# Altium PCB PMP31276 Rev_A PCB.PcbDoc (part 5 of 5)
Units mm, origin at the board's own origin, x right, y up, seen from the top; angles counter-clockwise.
Board outline 228.6 x 203.2 mm, 4 copper layers (Top Layer, Layer 1, Layer 2, Bottom Layer), stack 1.998 mm thick; 375 components, 187 nets, 994 pads, 546 vias.
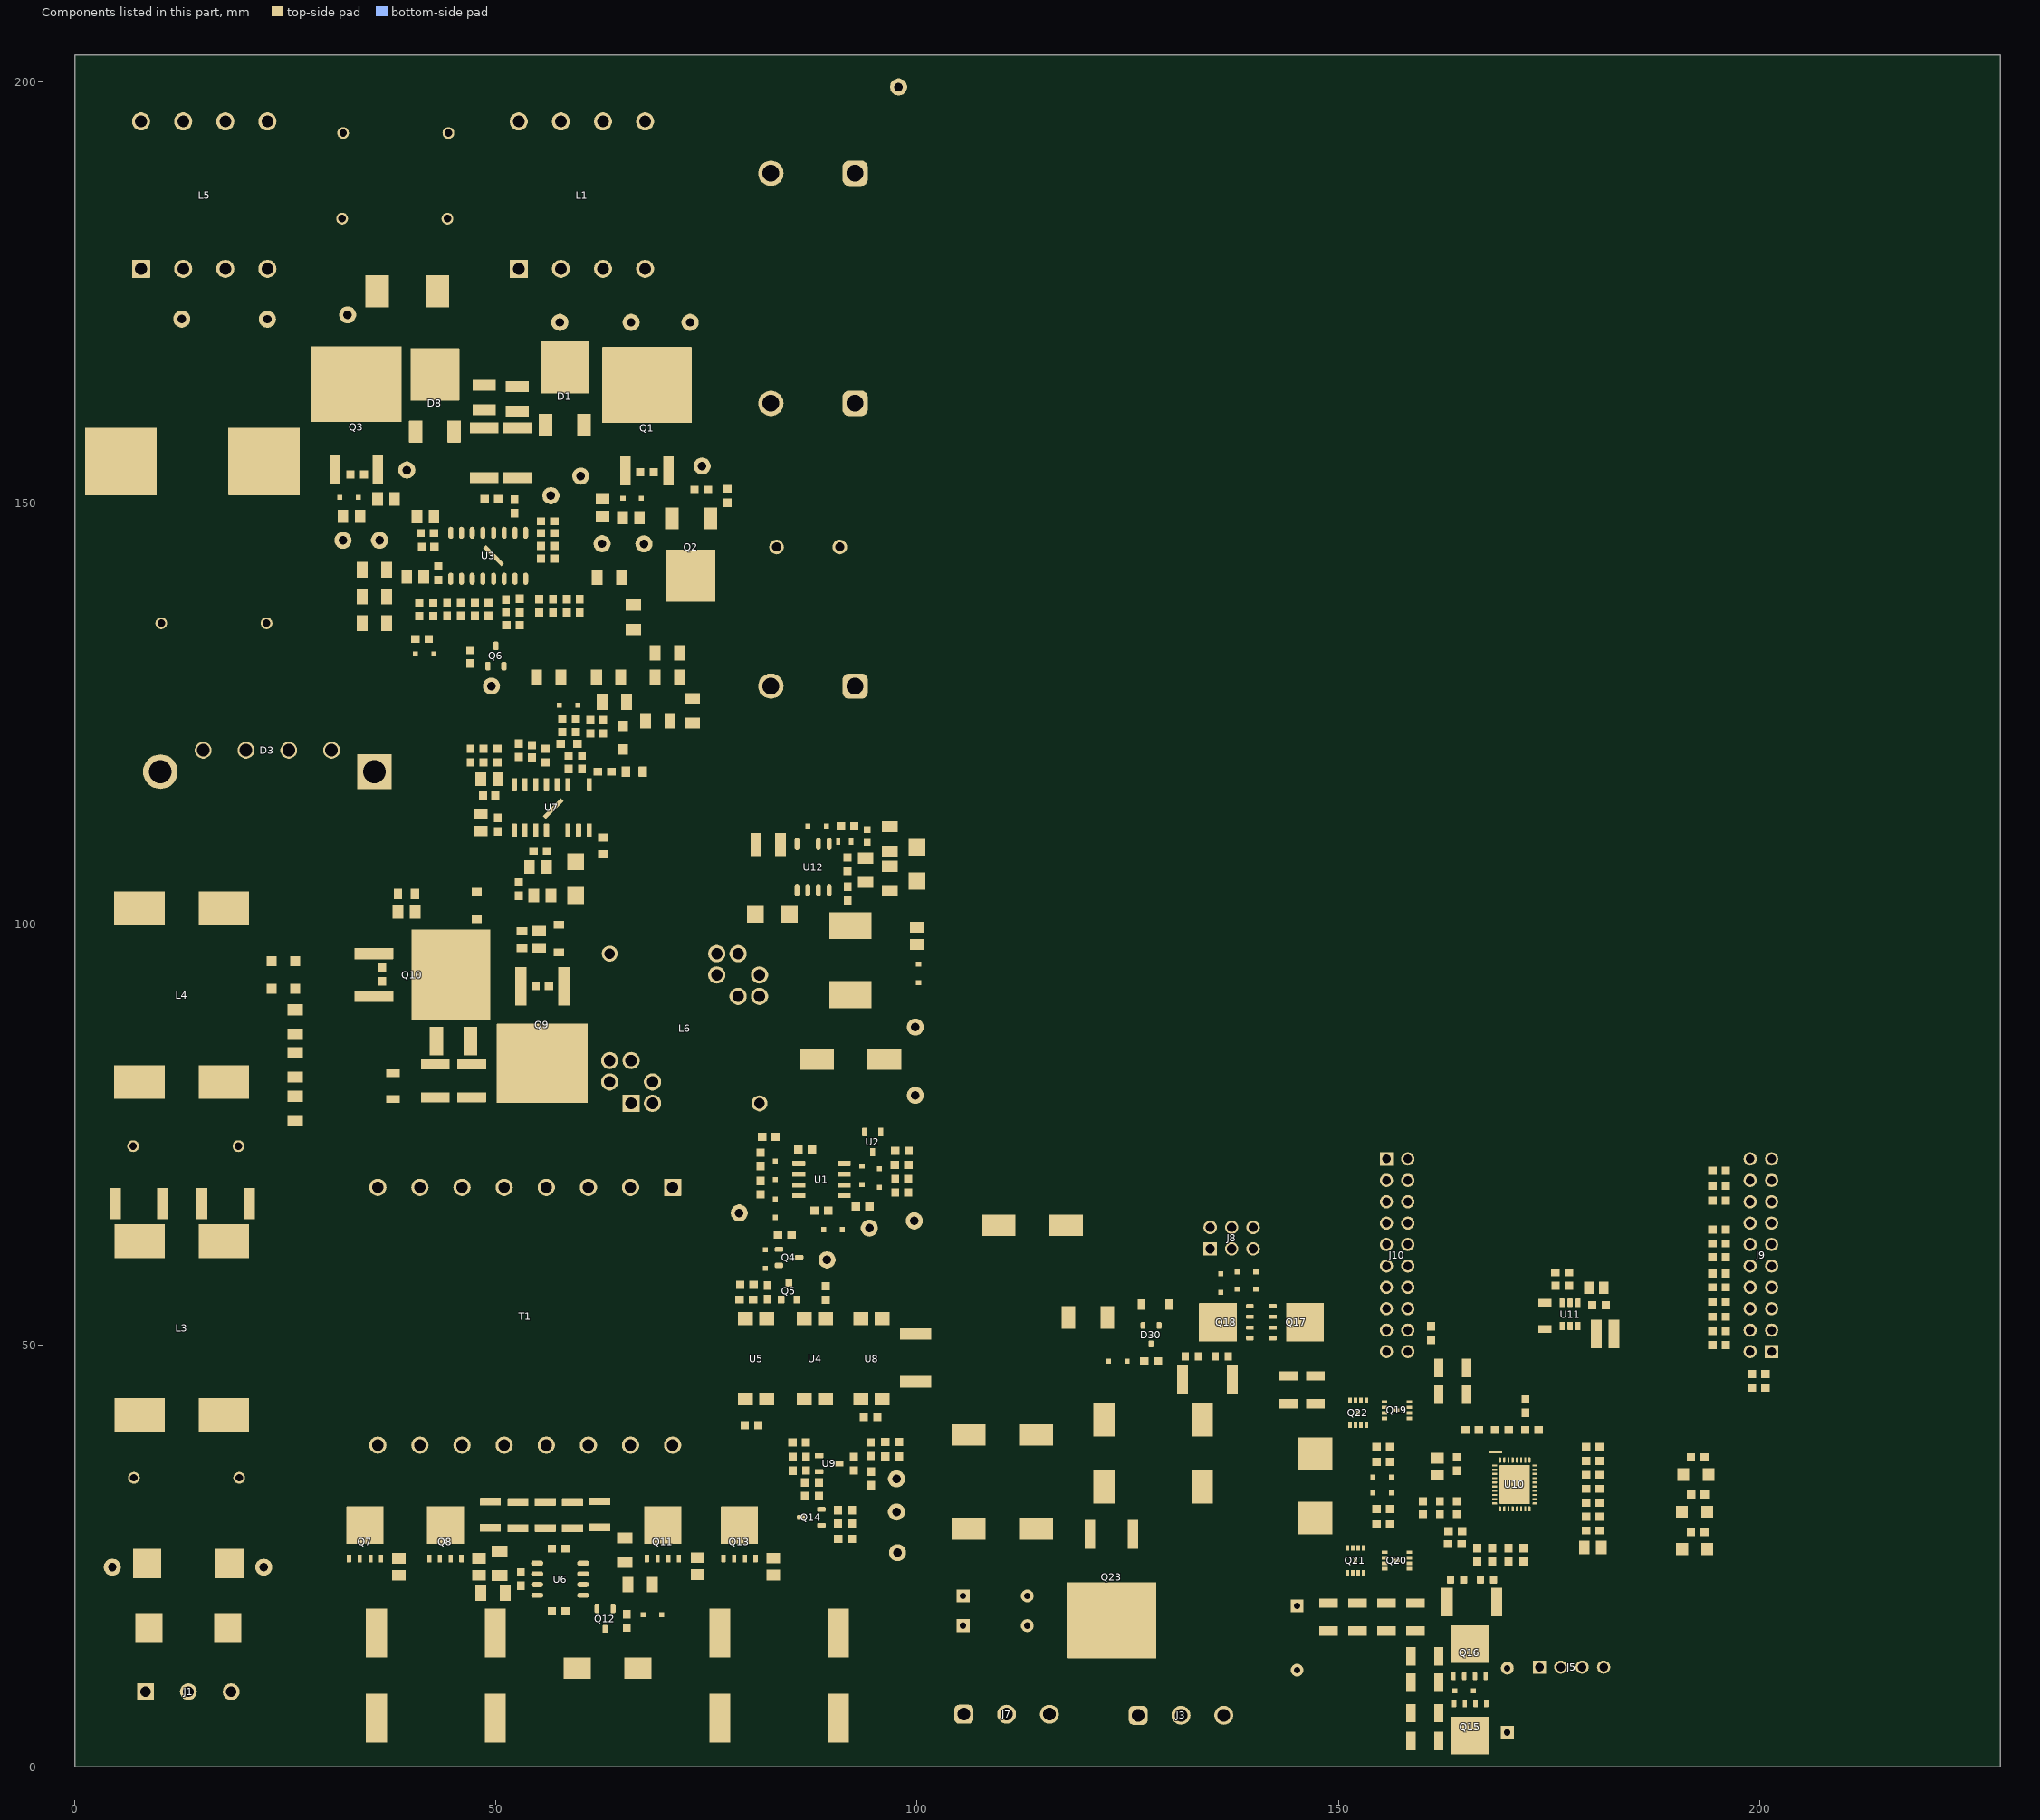
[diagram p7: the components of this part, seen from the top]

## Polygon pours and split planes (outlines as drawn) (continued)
NetC14_1 on Top Layer "TOP_LAYER_NETC14_1_P054" (solid, remove dead copper, pour order 54): 76.427,150.725 76.745,151.043 78.082,151.043 78.195,151.156 78.195,152.172 77.986,152.381 75.813,152.381 75.655,152.539 74.887,152.539 74.472,152.124 74.472,146.875 74.761,146.586 76.037,146.586 76.427,146.976
NetD11_2 on Top Layer "TOP_LAYER_NETD11_2_P053" (solid, remove dead copper, pour order 53): 18 vertices, not listed, extent 29.685,144.03 33.43,156.417
PGND on Top Layer "TOP_LAYER_PGND_P052" (solid, remove dead copper, pour order 52): 45.212,156.368 34.339,156.368 33.782,155.812 33.782,152.635 34.895,151.522 44.375,151.522 45.268,152.415
PGND on Top Layer "TOP_LAYER_PGND_P051" (solid, remove dead copper, pour order 51): 52.6,155.485 67.246,155.485 68.586,154.145 72.242,154.145 72.82,154.723 72.657,154.887 72.657,157.04 70.928,158.768 64.745,158.768 63.465,157.489 55.217,157.489 54.275,158.43 54.275,158.448 53.016,158.448 52.569,158
net_D1_3 on Top Layer "TOP_LAYER_NET_D1_3_P045" (solid, remove dead copper, pour order 45): 18 vertices, not listed, extent 59.283,158 73.895,197.231
PGND on Top Layer "TOP_LAYER_PGND_P050" (solid, remove dead copper, pour order 50): 70.356,146.28 69.193,145.118 69.193,144.02 68.356,143.182 65.886,143.182 65.886,146.025 66.673,146.812 67.799,146.812 68.336,147.349 68.336,154.723 70.318,156.706 72.122,156.706 74.053,154.774 74.053,148.343 71.99,146.28
Vpfc on Top Layer "TOP_LAYER_VPFC_P047" (solid, remove dead copper, pour order 47): 70.623,133.107 70.623,127.698 72.222,126.099 74.37,126.099 74.37,132.214 73.202,133.382 70.898,133.382
NetC1_2 on Top Layer "TOP_LAYER_NETC1_2_P046" (solid, remove dead copper, pour order 46): 17 vertices, not listed, extent 69.472,124.778 84.98,192.151
VAC on Top Layer "TOP_LAYER_VAC_P044" (solid, remove dead copper, pour order 44): 35.464,191.747 40.346,196.629 48.26,196.629 50.546,194.343 50.546,194.056 51.562,193.04 52.959,193.04 54.356,194.437 54.356,196.088 51.181,199.263 31.75,199.263 30.099,197.612 30.099,193.039 31.391,191.747
Vpfc on Top Layer "TOP_LAYER_VPFC_P043" (solid, remove dead copper, pour order 43): 21 vertices, not listed, extent 39.648,161.88 61.448,177.165
VAC on Top Layer "TOP_LAYER_VAC_P042" (solid, remove dead copper, pour order 42): 26.162,150.259 18.402,150.259 14.605,154.057 14.605,158.496 4.318,168.783 4.318,197.104 8.785,197.104 10.414,195.475 10.414,178.399 10.196,178.181 10.196,171.803 20.231,161.768 23.833,161.768 27.178,158.423 27.178,151.44
NetD8_3 on Top Layer "TOP_LAYER_NETD8_3_P039" (solid, remove dead copper, pour order 39): 18 vertices, not listed, extent 20.066,159.21 38.966,197.294
VAC on Top Layer "TOP_LAYER_VAC_P038" (solid, remove dead copper, pour order 38): 39.537,173.62 39.537,177.97 37.988,179.519 35.916,179.519 34.395,177.998 34.395,172.609 34.665,172.339 38.256,172.339
AGND1 on Top Layer "TOP_LAYER_AGND1_P037" (solid, remove dead copper, pour order 37): 58.427,142.068 41.855,142.068 39.769,144.154 39.769,146.586 40.339,147.156 41.596,147.156 41.968,146.784 41.968,144.417 42.649,143.736 54.657,143.736 56.134,145.214 56.134,146.849 56.388,147.103 57.393,147.103 58.427,146.068
AGND1 on Top Layer "TOP_LAYER_AGND1_P035" (solid, remove dead copper, pour order 35): 39.796,137.692 49.552,137.692 51.551,139.691 53.146,139.691 55.041,137.795 60.827,137.795 61.305,137.316 61.305,134.685 58.463,131.843 43.511,131.843 39.796,135.557
PGND on Top Layer "TOP_LAYER_PGND_P034" (solid, remove dead copper, pour order 34): 47.789,155.411 46.332,156.868 46.332,161.768 46.944,162.38 53.825,162.38 54.61,161.595 54.61,156.21 53.811,155.411
NetC6_2 on Top Layer "TOP_LAYER_NETC6_2_P032" (solid, remove dead copper, pour order 32): 13.688,118.991 5.08,127.599 5.08,145.776 1.016,149.84 1.016,159.438 2.36,160.782 10.196,160.782 11.938,159.04 11.938,133.512 17.266,128.184 17.266,120.142 16.115,118.991
NetD3_3 on Top Layer "TOP_LAYER_NETD3_3_P031" (solid, remove dead copper, pour order 31): 13.843,99.246 13.843,108.217 17.386,111.76 19.999,111.76 23.492,115.253 23.492,121.663 24.511,122.682 26.663,122.682 27.407,121.938 27.407,113.259 21.688,107.54 21.688,99.666
NetD3_2 on Top Layer "TOP_LAYER_NETD3_2_P030" (solid, remove dead copper, pour order 30): 3.302,97.184 10.588,97.184 11.71,98.306 11.71,108.484 16.51,113.284 18.365,113.284 22.225,117.144 22.225,122.174 21.717,122.682 19.812,122.682 18.365,121.235 18.365,119.146 16.778,117.56 15.452,117.56 3.302,105.41
NetD3_3 on Top Layer "TOP_LAYER_NETD3_3_P028" (solid, remove dead copper, pour order 28): 13.843,104.394 13.843,97.282 16.891,94.234 24.011,94.234 24.765,94.988 24.765,96.931 24.447,97.248 23.225,97.248 21.688,98.786 21.688,103.783 20.188,105.283 14.732,105.283
NetD3_2 on Top Layer "TOP_LAYER_NETD3_2_P027" (solid, remove dead copper, pour order 27): 3.302,104.648 3.302,93.583 5.826,91.059 24.13,91.059 24.765,91.694 24.765,93.084 24.266,93.583 14.498,93.583 11.688,96.393 11.71,96.415 11.71,104.254 10.681,105.283 4.434,105.283
NetC10_1 on Top Layer "TOP_LAYER_NETC10_1_P026" (solid, remove dead copper, pour order 26): 3.462,59.276 2.54,60.198 2.54,82.901 3.619,83.98 10.979,83.98 11.7,83.259 11.7,78.756 8.461,75.517 8.461,64.828 8.944,64.345 11.089,64.345 11.7,63.734 11.7,60.022 10.954,59.276
NetC11_1 on Top Layer "TOP_LAYER_NETC11_1_P025" (solid, remove dead copper, pour order 25): 5.465,20.193 3.175,22.483 3.175,43.224 6.052,46.101 11.2,46.101 12.226,45.075 12.226,23.536 8.883,20.193 8.802,20.193
NetC11_2 on Top Layer "TOP_LAYER_NETC11_2_P022" (solid, remove dead copper, pour order 22): 21.994,44.935 21.994,28.125 23.749,26.359 23.749,21.082 22.86,20.193 15.708,20.193 14.732,21.169 14.732,45.312 15.521,46.101 20.828,46.101
NetC94_2 on Layer 2 "LAYER_2_NETC94_2_P146" (solid, remove dead copper, pour order 146): 21 vertices, not listed, extent 83.82,98.035 101.05,113.284
SGND on Layer 2 "LAYER_2_SGND_P132" (solid, remove dead copper, pour order 132): 21 vertices, not listed, extent 29.782,0.723 106.813,46.482
SGND on Layer 2 "LAYER_2_SGND_P131" (solid, remove dead copper, pour order 131): 95.377,0.723 197.065,0.723 204.724,8.382 204.724,73.406 202.057,76.073 114.456,76.073 104.636,66.253 104.636,49.522 95.377,42.203
NetC75_1 on Layer 2 "LAYER_2_NETC75_1_P121" (solid, remove dead copper, pour order 121): 120.523,38.517 124.028,38.517 129.535,44.024 139.111,44.024 139.707,44.62 139.707,47.324 139.107,47.924 124.148,47.924 120.523,44.299
AGND on Layer 2 "LAYER_2_AGND_P102" (solid, remove dead copper, pour order 102): 21 vertices, not listed, extent 160.714,23.26 184.117,41.333
+24V on Layer 2 "LAYER_2_+24V_P008" (solid, remove dead copper, pour order 8): 71.665,9.271 73.189,10.795 78.74,10.795 79.738,11.793 79.738,18.71 78.522,19.926 74.491,19.926 73.66,19.095 73.66,16.924 72.356,15.62 67.08,15.62 64.456,12.996 64.456,10.166 65.351,9.271
VDS2 on Layer 2 "LAYER_2_VDS2_P082" (solid, remove dead copper, pour order 82): 73.052,40.559 82.219,31.393 82.219,26.669 81.898,26.348 64.32,26.348 63.842,26.826 63.842,31.034 64.407,31.598 64.407,39.799 65.166,40.559
VDS1 on Layer 2 "LAYER_2_VDS1_P072" (solid, remove dead copper, pour order 72): 33.712,40.57 29.782,36.64 29.782,27.27 30.693,26.359 48.226,26.359 48.226,30.155 43.539,34.841 43.539,38.338 41.307,40.57
Vpfc on Layer 2 "LAYER_2_VPFC_P049" (solid, remove dead copper, pour order 49): 84.711,123.534 78.564,123.534 68.658,113.628 68.658,111.818 65.18,111.818 49.25,95.888 49.25,73.157 50.234,72.173 73.552,72.173 73.552,101.346 97.79,125.222 97.79,131.191 88.898,128.951 88.898,127.721
Vpfc on Layer 2 "LAYER_2_VPFC_P041" (solid, remove dead copper, pour order 41): 72.319,126.002 74.229,126.002 79.534,131.307 92.757,131.307 92.757,133.678 92.45,133.985 71.501,133.985 70.623,133.107 70.623,127.698
Vpfc on Layer 2 "LAYER_2_VPFC_P029" (solid, remove dead copper, pour order 29): 17 vertices, not listed, extent 47.681,123.825 98.044,192.659
CS on Layer 2 "LAYER_2_CS_P023" (solid, remove dead copper, pour order 23): 42.037,194.062 42.037,157.644 39.583,155.19 40.722,154.051 45.215,154.051 46.536,155.372 44.921,156.987 44.921,180.356 46.834,182.269 46.834,194.562 45.583,195.813 43.788,195.813
VAC on Layer 2 "LAYER_2_VAC_P021" (solid, remove dead copper, pour order 21): 21 vertices, not listed, extent 4.97,170.307 39.537,197.104
CS on Layer 2 "LAYER_2_CS_P017" (solid, remove dead copper, pour order 17): 17 vertices, not listed, extent 18.542,118.11 55.12,158.377
+24V on Bottom Layer "Bottom Layer-+24V" (solid, remove dead copper, pour order 149): 17 vertices, not listed, extent 69.831,1.016 189.357,28.759
NetC81_1 on Bottom Layer "BOTTOM_LAYER_NETC81_1_P143" (solid, remove dead copper, pour order 143): 153.993,39.559 153.528,39.094 153.528,37.944 150.497,34.913 145.193,34.913 144.643,35.463 144.643,39.094 145.554,40.005 148.685,40.005 149.098,40.418 149.098,41.025 150.368,42.294 153.698,42.294 153.993,42
NetC80_1 on Bottom Layer "BOTTOM_LAYER_NETC80_1_P142" (solid, remove dead copper, pour order 142): 155.87,23.883 147.725,23.883 144.898,26.71 144.898,31.31 145.428,31.839 149.617,31.839 154.45,27.007 154.45,26.128 154.766,25.811 155.721,25.811 155.87,25.663
SYSTEM on Bottom Layer "BOTTOM_LAYER_SYSTEM_P108" (solid, remove dead copper, pour order 108): 18 vertices, not listed, extent 129.907,17.575 160.282,55.042
NetC81_1 on Bottom Layer "BOTTOM_LAYER_NETC81_1_P104" (solid, remove dead copper, pour order 104): 150.613,39.972 153.615,39.972 153.993,40.35 153.993,40.876 154.907,41.791 155.87,41.791 155.87,43.527 155.612,43.785 154.777,43.785 153.492,42.5 150.573,42.5 150.368,42.294 150.368,40.217
+24Vsw on Bottom Layer "BOTTOM_LAYER_+24VSW_P096" (solid, remove dead copper, pour order 96): 44.457,39.497 44.457,34.795 48.397,30.855 62.695,30.855 63.444,31.604 63.444,39.088 61.962,40.57 45.53,40.57
VDS2 on Bottom Layer "BOTTOM_LAYER_VDS2_P076" (solid, remove dead copper, pour order 76): 73.052,40.559 82.219,31.393 82.219,26.669 81.898,26.348 64.32,26.348 63.842,26.826 63.842,31.034 64.407,31.598 64.407,39.799 65.166,40.559
VDS1 on Bottom Layer "BOTTOM_LAYER_VDS1_P075" (solid, remove dead copper, pour order 75): 33.712,40.57 29.782,36.64 29.782,27.38 30.803,26.359 47.246,26.359 47.246,30.668 43.539,34.375 43.539,38.338 41.307,40.57
EARTH on Bottom Layer "BOTTOM_LAYER_EARTH_P073" (solid, remove dead copper, pour order 73): 16.764,7.239 19.854,7.239 21.411,8.796 21.411,64.509 16.129,69.79 9.973,69.79 9.271,69.088 9.271,18.288 15.708,11.851 15.708,8.89
PGND on Bottom Layer "BOTTOM_LAYER_PGND_P069" (solid, remove dead copper, pour order 69): 20 vertices, not listed, extent 25.146,50.546 101.981,202.057
SGND on Layer 1 "LAYER_1_SGND_P140" (solid, remove dead copper, pour order 140): 23 vertices, not listed, extent 91.615,0.723 204.724,76.327
+24Vsw on Layer 1 "LAYER_1_+24VSW_P067" (solid, remove dead copper, pour order 67): 23 vertices, not listed, extent 31.747,10.37 93.517,40.567
SGND on Layer 1 "LAYER_1_SGND_P100" (solid, remove dead copper, pour order 100): 100.152,22.123 100.152,44.013 99.145,45.02 75.467,45.02 75.467,39.889 84.002,31.354 84.002,26.755 83.077,25.83 83.077,21.532
SGND on Layer 1 "LAYER_1_SGND_P092" (solid, remove dead copper, pour order 92): 29.782,24.62 29.782,4.89 33.949,0.723 97.65,0.723 100.152,3.225 100.152,24.217 98.363,26.006 53.805,26.006 51.881,24.082 46.542,24.082 45.307,25.317 30.48,25.317
VDS2 on Layer 1 "LAYER_1_VDS2_P091" (solid, remove dead copper, pour order 91): 73.052,40.559 82.219,31.393 82.219,26.669 81.898,26.348 64.32,26.348 63.842,26.826 63.842,31.034 64.407,31.598 64.407,39.799 65.166,40.559
VDS1 on Layer 1 "LAYER_1_VDS1_P071" (solid, remove dead copper, pour order 71): 33.712,40.57 29.782,36.64 29.782,27.38 30.803,26.359 48.226,26.359 48.226,30.155 47.759,30.155 43.539,34.375 43.539,38.338 41.307,40.57

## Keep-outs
Keep-Out Layer:
  text ".Layer_Name" at 14.656,-21.806 h1.52

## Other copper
Top Layer:
  text ".Layer_Name" at 14.656,-21.806 h1.52
Bottom Layer:
  text ".Layer_Name" at 14.656,-21.806 h1.52

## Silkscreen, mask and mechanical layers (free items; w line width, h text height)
Top Overlay:
  lines w0.3: 106.426,106.656 105.156,107.188 ; 106.426,107.696 105.156,107.188 ; 108.204,107.188 105.156,107.188
  text "Vpfc" at 99.847,199.238 h0.76
  text "NWA" at 99.636,33.503 h0.76
  text "SGND" at 99.636,24.97 h0.76
  text "System" at 140.168,3.775 h0.76 r90
  text "Earth" at 17.501,3.658 h0.76
  text "Battery" at 102.182,3.648 h0.76 r90
  text "'.PRJ_Number'.PCB_Rev" at 59.074,1.27 h2.75
  text "IN" at 11.729,1.118 h1
  text ".Layer_Name" at 14.656,-21.806 h1.52
Bottom Overlay:
  text ".Layer_Name" at 14.656,-21.806 h1.52
Top Paste:
  text ".Layer_Name" at 14.656,-21.806 h1.52
Bottom Paste:
  text ".Layer_Name" at 14.656,-21.806 h1.52
Top Solder:
  text ".Layer_Name" at 14.656,-21.806 h1.52
  text ".Layer_Name" at 14.656,-21.806 h1.52
Bottom Solder:
  text ".Layer_Name" at 14.656,-21.806 h1.52
Drill Guide:
  text ".Layer_Name" at 14.656,-21.806 h1.52
M1 Board Outline:
  the board outline again, w0.254
  text ".Layer_Name" at 14.656,-21.806 h1.52
M2 Board Dimensions:
  rectangle: 0,-6.985 3.175,-3.81
  rectangle: 3.175,-10.16 12.7,-6.985
  lines w0.178: 0,-6.985 25.4,-6.985 ; 3.175,-10.16 3.175,-3.81 ; 6.35,-10.16 6.35,-3.81 ; 12.7,-10.16 12.7,-3.81 ; 19.05,-10.16 19.05,-3.81 ; 0,-10.16 25.4,-10.16 25.4,-3.81 0,-3.81 0,-10.16
  text ".Layer_Name" at 14.656,-21.806 h1.52
M3 3D STEP Top:
  text ".Layer_Name" at 14.656,-21.806 h1.52
M4 3D STEP Bottom:
  text ".Layer_Name" at 14.656,-21.806 h1.52
M5 Assembly Top:
  lines w0.254: -7.417,-23.626 160.223,-23.626 ; -7.417,-18.462 160.274,-18.462 ; -7.417,-13.297 -7.417,-28.791 94.31,-28.791 160.274,-28.791 160.274,-13.297 -7.404,-13.297 -7.404,-28.791 32.614,-28.791 ; 55.194,-28.791 55.194,-13.297 ; 87.376,-18.462 87.376,-13.297 ; 108.712,-18.462 108.712,-13.297 ; 124.511,-28.956 124.511,-23.804
  text "COMPONENTS MARKED 'DNP' SHOULD NOT BE POPULATED." at 29.299,-8.09 h1.52
  text "ASSEMBLY VARIANT:" at 29.286,-11.024 h1.52
  text ".VariantName" at 55.601,-11.024 h1.52
  text "PCB VIEWED FROM TOP SIDE" at -5.804,-16.654 h1.52
  text "BOARD #:" at 57.099,-16.654 h1.52
  text ".PRJ_Number" at 70.955,-16.654 h1.52
  text "REV:" at 92.405,-16.654 h1.52
  text ".PCB_Rev" at 99.809,-16.654 h1.52
  text "SVN REV:" at 113.69,-16.654 h1.52
  text ".VersionControl_RevNumber" at 126.543,-16.654 h1.52
  text "TID #:" at 57.099,-21.819 h1.52
  text ".TID" at 70.955,-21.819 h1.52
  text "PLOT NAME =" at -5.804,-27.034 h1.52
  text ".plot_File_Name" at 14.656,-27.034 h1.52
  text "GENERATED    :" at 57.15,-27.034 h1.52
  text ".Print_Date" at 79.235,-27.034 h1.52
  text ".Print_Time" at 97.752,-27.034 h1.52
  text "TEXAS INSTRUMENTS" at 129.87,-27.034 h1.52
M6 Assembly Bottom:
  lines w0.254: -7.429,-18.474 160.261,-18.474 ; -7.379,-23.639 160.261,-23.639 ; 28.334,-28.969 28.334,-23.817 ; 44.133,-18.474 44.133,-13.31 ; 65.468,-18.474 65.468,-13.31 ; 97.65,-28.804 97.65,-13.31 ; 120.231,-28.804 160.249,-28.804 160.249,-13.31 -7.429,-13.31 -7.429,-28.804 58.534,-28.804 160.261,-28.804 160.261,-13.31
  text "COMPONENTS MARKED 'DNP' SHOULD NOT BE POPULATED." at 154.991,-8.077 h1.52
  text ".VariantName" at 128.473,-11.024 h1.52
  text "ASSEMBLY VARIANT:" at 154.864,-11.024 h1.52
  text ".VersionControl_RevNumber" at 26.302,-16.667 h1.52
  text "SVN REV:" at 39.154,-16.667 h1.52
  text ".PCB_Rev" at 53.035,-16.667 h1.52
  text "REV:" at 60.439,-16.667 h1.52
  text ".PRJ_Number" at 81.89,-16.667 h1.52
  text "BOARD #:" at 95.745,-16.667 h1.52
  text "PCB VIEWED FROM BOTTOM SIDE" at 158.648,-16.667 h1.52
  text ".TID" at 81.89,-21.831 h1.52
  text "TID #:" at 95.745,-21.831 h1.52
  text "TEXAS INSTRUMENTS" at 22.974,-27.047 h1.52
  text ".Print_Time" at 55.093,-27.047 h1.52
  text ".Print_Date" at 73.609,-27.047 h1.52
  text "GENERATED    :" at 95.694,-27.047 h1.52
  text ".plot_File_Name" at 138.189,-27.047 h1.52
  text "PLOT NAME =" at 158.648,-27.047 h1.52
M9 Title Sheet:
  drawing of 57 lines, arcs and shapes, not listed
  text "1" at 18.792,204.127 h1.78
  text "2" at 82.182,204.127 h1.78
  text "3" at 145.411,204.127 h1.78
  text "4" at 209.08,204.127 h1.78
  text "5" at 272.555,204.127 h1.78
  text "6" at 336.182,204.127 h1.78
  text "A" at -10.579,175.095 h1.78
  text "A" at 365.341,175.095 h1.78
  text "B" at -10.579,114.643 h1.78
  text "B" at 365.341,114.643 h1.78
  text "C" at -10.579,54.318 h1.78
  text "C" at 365.341,54.318 h1.78
  text "PROJECT TITLE:" at 288.125,7.048 h1.14
  text ".PRJ_Title" at 289.395,3.662 h1.78
  text "DESIGNED FOR:" at 288.125,-0.597 h1.14
  text ".PRJ_Customer" at 289.395,-4.153 h1.78
  text "D" at -10.579,-5.88 h1.78
  text "D" at 365.341,-5.88 h1.78
  text "FILE NAME:" at 288.125,-8.217 h1.14
  text ".PCB_File_Name_No_Path" at 289.395,-11.265 h1.78
  text "Texas Instruments (TI) and/or its licensors do not warrant the accuracy or completeness of this specification" at 161.9,-15.376 h1.14
  text "ENGINEER:" at 288.125,-15.583 h1.14
  text "LAYOUT BY:" at 326.352,-15.583 h1.14
  text "or any information contained therein. TI and/or its licensors do not warrant that this design will meet" at 160.757,-18.237 h1.14
  text ".PRJ_Engineer" at 289.395,-19.52 h1.78
  text ".PCB_Layout" at 327.635,-19.52 h1.78
  text "the specifications, will be suitable for your application or fit for any particular purpose, or will operate in" at 160.757,-21.099 h1.14
  text ".Layer_Name" at 14.656,-21.806 h1.52
  text "ALTIUM DESIGNER VERSION:" at 326.352,-23.457 h1.14
  text "an implementation. TI and/or its licensors do not warrant that the design is production worthy. You should" at 160.757,-23.961 h1.14
  text "completely validate and test your design implementation to confirm the system functionality for your application." at 161.9,-26.822 h1.14
  text ".print_Scale" at 289.395,-26.843 h1.78
  text ".Application_BuildNumber" at 327.635,-26.843 h1.78
  text "1" at 18.792,-32.093 h1.78
  text "2" at 82.182,-32.093 h1.78
  text "3" at 145.411,-32.093 h1.78
  text "4" at 209.08,-32.093 h1.78
  text "5" at 272.555,-32.093 h1.78
  text "6" at 336.182,-32.093 h1.78
M10 Fab Notes:
  drawing of 189 lines, arcs and shapes, not listed
  text "DESIGN INFORMATION" at 314.503,161.447 h1.52
  text "MIN. TRACK WIDTH:" at 298.131,158.091 h1.52
  text "8" at 325.976,158.091 h1.52
  text "MIL" at 329.907,158.091 h1.52
  text "7.874" at 321.75,155 h1.52
  text "MIN. CLEARANCE:" at 298.131,154.938 h1.52
  text "MIL" at 329.907,154.938 h1.52
  text "MIN. VIA PAD SIZE:" at 298.131,151.785 h1.52
  text "24" at 325.214,151.785 h1.52
  text "MIL" at 329.907,151.785 h1.52
  text "0.05mm (2MIL)" at 315.784,148.486 h1.52
  text "MINIMUM ANNULAR RING" at 289.769,148.277 h1.52
  text "EXTERNAL" at 333.768,148.277 h1.52
  text "PER" at 294.849,145.48 h1.52
  text "IPC-D-275 CLASS 2 LEVEL C" at 300.437,145.48 h1.52
  text "MIL, HOLES" at 338.238,142.928 h1.52
  text "+/-" at 328.27,142.709 h1.52
  text "+/-" at 349.961,142.709 h1.52
  text "REGISTRATION TOLERANCES:" at 289.769,142.682 h1.52
  text "METAL" at 320.243,142.682 h1.52
  text "5" at 334.879,142.683 h1.52
  text "3" at 356.037,142.683 h1.52
  text "MIL" at 358.99,142.682 h1.52
  text "HOLE SIZE TOLERANCE (UNLESS OTHERWISE SPECIFIED):" at 289.769,140.185 h1.52
  text "+/-" at 349.961,140.112 h1.52
  text "3" at 356.037,140.085 h1.52
  text "MIL" at 358.99,140.085 h1.52
  text "MATERIAL:" at 287.87,136.589 h1.52
  text "FR-4 High Tg" at 312.926,133.324 h1.52
  text "X" at 309.257,133.122 h1.52
  text "FR-4" at 298.563,133.007 h1.52
  text "OTHER" at 336.358,133.007 h1.52
  text "62 MIL (1.6mm) +/-10%" at 306.694,129.374 h1.52
  text "X" at 303.643,129.312 h1.52
  text "THICKNESS:" at 289.769,129.165 h1.52
  text "OTHER" at 339.33,129.165 h1.52
  text "TOLERANCE:" at 289.769,125.652 h1.52
  text "X" at 311.314,125.652 h1.52
  text "ANSI IPC-6012 TYPE 3 CLASS 2" at 315.836,125.652 h1.52
  text "OTHER +/-" at 315.835,121.989 h1.52
  text "BOW & TWIST:" at 289.769,118.302 h1.52
  text "X" at 311.314,118.302 h1.52
  text "ANSI IPC-6012 TYPE 3 CLASS 2" at 315.836,118.302 h1.52
  text "OTHER +/-" at 315.835,114.576 h1.52
  text "DRILLING:" at 287.87,111.258 h1.52
  text "NC_DRILL FILES" at 332.599,108.586 h1.52
  text "REFERENCE:" at 289.769,108.486 h1.52
  text "X" at 306.463,108.484 h1.52
  text "AS SHOWN" at 310.984,108.486 h1.52
  text "X" at 329.348,108.486 h1.52
  text "OTHER" at 340.168,104.873 h1.52
  text "PTH COPPER THICKNESS:" at 289.761,104.783 h1.52
  text "X" at 318.697,104.783 h1.52
  text "20-30 um" at 321.948,104.783 h1.52
  text "BOARD FINISH:" at 287.87,101.034 h1.52
  text "SILKSCREEN:" at 291.812,98.237 h1.52
  text "X" at 316.14,98.237 h1.52
  text "TOP" at 319.112,98.237 h1.52
  text "X" at 329.094,98.237 h1.52
  text "BOTTOM" at 332.091,98.237 h1.52
  text "SILKSCREEN COLOR:" at 291.812,94.295 h1.52
  text "X" at 316.115,94.295 h1.52
  text "WHITE" at 319.112,94.295 h1.52
  text "OTHER" at 332.091,94.295 h1.52
  text "X" at 319.442,90.652 h1.52
  text "GREEN" at 322.439,90.652 h1.52
  text "OTHER" at 338.136,90.652 h1.52
  text "SOLDER RESIST COLOR:" at 291.812,90.477 h1.52
  text "X" at 319.442,86.734 h1.52
  text "MATTE" at 322.439,86.734 h1.52
  text "SEMI-GLOSS" at 338.125,86.717 h1.52
  text "IMMERSION GOLD (ENIG)" at 314.819,82.345 h1.52
  text "ENEPIG" at 348.793,82.162 h1.52
  text "SURFACE FINISH:" at 287.87,82.136 h1.52
  text "X" at 310.298,82.136 h1.52
  text "IMM. TIN/SILVER OR EQUIV" at 296.24,78.649 h1.52
  text "OTHER" at 332.599,78.549 h1.52
  text "ARRAY/PANEL:" at 287.87,74.602 h1.52
  text "CUT AND TRIM PER M1 BOARD OUTLINE" at 314.819,74.393 h1.52
  text "N.C. ROUTE" at 314.819,70.94 h1.52
  text "X" at 332.295,70.94 h1.52
  text "V. SCORE" at 336.816,70.94 h1.52
  text "CERTIFICATION:" at 287.87,67.66 h1.52
  text "MATERIALS AND WORKMANSHIP FOR ALL PCBS" at 306.285,67.66 h1.52
  text "TO MEET OR EXCEED THE REQUIREMENTS OF:" at 306.285,65.271 h1.52
  text "X" at 297.078,62.003 h1.52
  text "ANSI IPC-A-600F CLASS ->" at 300.329,62.003 h1.52
  text "X" at 342.188,62.003 h1.52
  text "2" at 344.982,62.003 h1.52
  text "1" at 336.981,61.965 h1.52
  text "3" at 353.973,61.965 h1.52
  text "X" at 317.702,58.252 h1.52
  text "RoHS" at 320.953,58.252 h1.52
  text "OTHER" at 337.321,58.252 h1.52
  text "PER ORDER" at 347.407,58.252 h1.52
  text "ALL BOARDS MUST MEET OR EXCEED UL94-V0 REQUIREMENTS." at 288.569,54.345 h1.52
  text "PCB MUST BEAR THE UL94V-0 UL REGISTERED MATERIAL ID NUMBER" at 288.569,51.397 h1.52
  text "ADDITIONAL REQUIREMENTS:" at 287.87,47.094 h1.52
  text "MICROSECTION:" at 289.769,44.373 h1.52
  text "YES" at 312.775,44.373 h1.52
  text "REQUIRED" at 334.657,40.707 h1.52
  text "BARE BOARD ELEC. TEST:" at 289.769,40.634 h1.52
  text "NONE" at 322.935,40.634 h1.52
  text "X" at 331.66,40.634 h1.52
  text "PER ORDER" at 349.693,40.634 h1.52
  text "XX MIL VIAS REQUIRE NON-CONDUCTIVE FILL AND PLANARIZE" at 294.04,35.428 h1.5
  text "XX MIL VIAS REQUIRE CONDUCTIVE FILL AND PLANARIZE" at 294.243,32.787 h1.52
  text "OUTER XX MIL TRACES REQUIRE 50 OHM SINGLE-ENDED IMPEDANCE" at 294.218,28.637 h1.47
  text "LAYER 2 & 3 (INNER LAYERS) XX MIL WIDE, XX MIL SPACE / TRACES REQUIRE 100 OHM DIFFERENTIAL IMPEDANCE" at 294.015,22.65 h1.52
  text ".Layer_Name" at 14.656,-21.806 h1.52
M11 Gerber Information:
  lines w0.254: -7.417,-23.626 160.223,-23.626 ; -7.417,-18.462 160.274,-18.462 ; -7.417,-13.297 -7.417,-28.791 94.31,-28.791 160.274,-28.791 160.274,-13.297 -7.404,-13.297 -7.404,-28.791 32.614,-28.791 ; 55.194,-28.791 55.194,-13.297 ; 87.376,-18.462 87.376,-13.297 ; 108.712,-18.462 108.712,-13.297 ; 124.511,-28.956 124.511,-23.804
  text "ALL ARTWORK VIEWED FROM TOP SIDE" at -5.804,-16.654 h1.52
  text "BOARD #:" at 57.099,-16.654 h1.52
  text ".PRJ_Number" at 70.955,-16.654 h1.52
  text "REV:" at 92.405,-16.654 h1.52
  text ".PCB_Rev" at 99.809,-16.654 h1.52
  text "SVN REV:" at 113.69,-16.654 h1.52
  text ".VersionControl_RevNumber" at 126.543,-16.654 h1.52
  text "LAYER NAME =" at -5.804,-21.806 h1.52
  text "TID #:" at 57.099,-21.819 h1.52
  text ".TID" at 70.955,-21.819 h1.52
  text "PLOT NAME =" at -5.804,-27.034 h1.52
  text ".plot_File_Name" at 14.656,-27.034 h1.52
  text "GENERATED    :" at 57.15,-27.034 h1.52
  text ".Print_Date" at 79.235,-27.034 h1.52
  text ".Print_Time" at 97.752,-27.034 h1.52
  text "TEXAS INSTRUMENTS" at 129.87,-27.034 h1.52
M12 Stackup:
  drawing of 347 lines, arcs and shapes, not listed
  text "Layer" at 249.469,200.023 h1.52
  text "Name" at 259.88,200.023 h1.52
  text "Material" at 283.496,200.023 h1.52
  text "Thickness" at 305.334,200.023 h1.52
  text "Constant" at 321.84,200.023 h1.52
  text "Board Layer Stack" at 336.314,200.023 h1.52
  text "Top Overlay" at 259.88,196.975 h1.52
  text "Top Solder" at 259.88,193.927 h1.52
  text "Solder Resist" at 283.496,193.927 h1.52
  text "0.40mil" at 305.334,193.927 h1.52
  text "3.5" at 321.84,193.927 h1.52
  text "1" at 249.469,190.879 h1.52
  text "Top Layer" at 259.88,190.879 h1.52
  text "2.76mil" at 305.334,190.879 h1.52
  text "Dielectric 1" at 259.88,187.831 h1.52
  text "PP-006" at 283.496,187.831 h1.52
  text "2.80mil" at 305.334,187.831 h1.52
  text "4.1" at 321.84,187.831 h1.52
  text "2" at 249.469,184.783 h1.52
  text "Layer 1" at 259.88,184.783 h1.52
  text "CF-004" at 283.496,184.783 h1.52
  text "1.38mil" at 305.334,184.783 h1.52
  text "Dielectric 3" at 259.88,181.735 h1.52
  text "PP-006" at 283.496,181.735 h1.52
  text "2.80mil" at 305.334,181.735 h1.52
  text "4.1" at 321.84,181.735 h1.52
  text "Dielectric1" at 259.88,178.687 h1.52
  text "FR-4 High Tg" at 283.496,178.687 h1.52
  text "59.20mil" at 305.334,178.687 h1.52
  text "4.8" at 321.84,178.687 h1.52
  text "Dielectric 4" at 259.88,175.639 h1.52
  text "PP-006" at 283.496,175.639 h1.52
  text "2.80mil" at 305.334,175.639 h1.52
  text "4.1" at 321.84,175.639 h1.52
  text "3" at 249.469,172.591 h1.52
  text "Layer 2" at 259.88,172.591 h1.52
  text "CF-004" at 283.496,172.591 h1.52
  text "1.38mil" at 305.334,172.591 h1.52
  text "Dielectric 2" at 259.88,169.543 h1.52
  text "PP-006" at 283.496,169.543 h1.52
  text "2.80mil" at 305.334,169.543 h1.52
  text "4.1" at 321.84,169.543 h1.52
  text "4" at 249.469,166.495 h1.52
  text "Bottom Layer" at 259.88,166.495 h1.52
  text "2.76mil" at 305.334,166.495 h1.52
  text "Bottom Solder" at 259.88,163.447 h1.52
  text "Solder Resist" at 283.496,163.447 h1.52
  text "0.40mil" at 305.334,163.447 h1.52
  text "3.5" at 321.84,163.447 h1.52
  text "Bottom Overlay" at 259.88,160.399 h1.52
  text ".Layer_Name" at 14.656,-21.806 h1.52
M13 Component Bodies Top:
  text ".Layer_Name" at 14.656,-21.806 h1.52
M14 Component Bodies Bottom:
  text ".Layer_Name" at 14.656,-21.806 h1.52
M15 Courtyards Top:
  text ".Layer_Name" at 14.656,-21.806 h1.52
M16 Courtyards Bottom:
  text ".Layer_Name" at 14.656,-21.806 h1.52
Drill Drawing:
  text ".Layer_Name" at 14.656,-21.806 h1.52
M17 Embedded Cavity:
  text ".Layer_Name" at 14.656,-21.806 h1.52
M18 Embedded Assembly:
  text ".Layer_Name" at 14.656,-21.806 h1.52
M19 Embedded Keepout:
  text ".Layer_Name" at 14.656,-21.806 h1.52

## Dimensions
0,-10.16 to 25.4,-10.16 on M2 Board Dimensions
0,0 to 0,203.2 on M2 Board Dimensions
0,0 to 228.6,0 on M2 Board Dimensions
